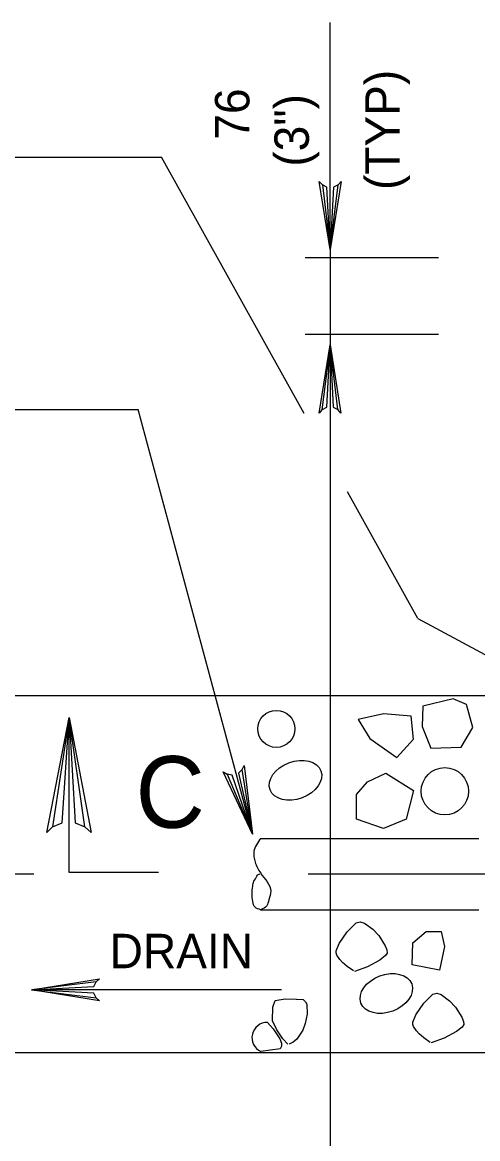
# Model space of a CAD drawing. Extents: x 638455 to 640199, y 298558 to 299152.
# Drawn here: x 639410.6 to 639455, y 298979.8 to 299088.8 of the extents above; entities that cross this region are included whole.
import ezdxf

# ---------------------------------------------------------------- set-up
doc = ezdxf.new("R2010")
doc.units = 0
for name, color, linetype in [('1', 7, 'Continuous'), ('2', 7, 'Continuous'), ('3', 7, 'Continuous')]:
    doc.layers.add(name, color=color, linetype=linetype)

msp = doc.modelspace()

# ---------------------------------------------------------------- linework, layer by layer
at = {"layer": '1'}
for p, q in [((639438.04, 299050.57), (639424.14, 299075.6)), ((639433.02, 299009.51), (639421.85, 299050.97)), ((639449.14, 299030.57), (639442.29, 299042.92))]:
    msp.add_line(p, q, dxfattribs=at)
for points in [[(639452.58, 299022.71), (639449.64, 299022.01), (639449.56, 299020), (639450.41, 299017.91), (639453.36, 299017.98), (639454.52, 299019.92), (639453.9, 299022.17)], [(639447.1, 299016.99), (639448.73, 299018.77), (639448.5, 299021.01), (639445.79, 299021.25), (639443.31, 299020.7), (639444.47, 299018.85)], [(639443.15, 299010.96), (639443.15, 299013.36), (639444.23, 299014.6), (639446.01, 299015.46), (639448.72, 299013.75), (639448.02, 299010.96), (639445.78, 299010.04)], [(639448.58, 298996.73), (639448.67, 298998.88), (639449.96, 298999.99), (639451.42, 298999.99), (639451.76, 298998.53), (639451.25, 298996.21)]]:
    msp.add_lwpolyline(points, close=True, dxfattribs=at)
for centre, radius in [((639435.34, 299019.78), 1.81), ((639451.78, 299013.69), 2.31)]:
    msp.add_circle(centre, radius, dxfattribs=at)
msp.add_arc((639434.45, 298989.63), 1.49, 89.5919, 244.8137, dxfattribs=at)
for centre in [(639437.21, 299014.76), (639446.07, 298993.94)]:
    msp.add_ellipse(centre, major_axis=(-2.48, -0.93), ratio=0.690668, dxfattribs=at)
at = {"layer": '2'}
for p, q in [((639440.59, 299066.59), (639440.59, 299088.77)), ((639395.61, 299075.6), (639424.14, 299075.6)), ((639451.15, 299065.79), (639438.15, 299065.79)), ((639440.59, 299066.59), (639440.59, 298952.92)), ((639451.15, 299058.29), (639438.15, 299058.29)), ((639391.01, 299050.97), (639421.85, 299050.97)), ((639449.14, 299030.57), (639476.21, 299015.92)), ((639373.94, 299023.03), (639513.29, 299023.03)), ((639415.11, 299005.77), (639415.11, 299020.89)), ((639433.8, 299009.09), (639455.11, 299009.09)), ((639367.29, 299005.61), (639411.68, 299005.61)), ((639423.83, 299005.77), (639415.11, 299005.77)), ((639438.43, 299005.61), (639589.81, 299005.61)), ((639433.8, 299002.12), (639455.11, 299002.12)), ((639373.95, 298988.18), (639513.29, 298988.18))]:
    msp.add_line(p, q, dxfattribs=at)
for points in [[(639441.38, 299072.92), (639440.92, 299072.68), (639440.59, 299066.59), (639441.38, 299072.92), (639441.66, 299073.24), (639440.59, 299066.59), (639440.28, 299072.68), (639439.83, 299072.9), (639440.59, 299066.59), (639439.53, 299073.24), (639439.83, 299072.9)], [(639439.79, 299050.94), (639440.25, 299051.18), (639440.59, 299057.28), (639439.79, 299050.94), (639439.51, 299050.62), (639440.59, 299057.28), (639440.89, 299051.19), (639441.34, 299050.96), (639440.59, 299057.28), (639441.64, 299050.62), (639441.34, 299050.96)], [(639413.5, 299010.2), (639414.43, 299010.59), (639415.11, 299020.89), (639413.5, 299010.2), (639412.94, 299009.65), (639415.11, 299020.89), (639415.72, 299010.6), (639416.65, 299010.23), (639415.11, 299020.89), (639417.26, 299009.65), (639416.65, 299010.23)], [(639432.01, 299015.8), (639431.64, 299015.45), (639433.02, 299009.51), (639432.01, 299015.8), (639432.19, 299016.19), (639433.02, 299009.51), (639431.03, 299015.27), (639430.53, 299015.35), (639433.02, 299009.51), (639430.14, 299015.6), (639430.53, 299015.35)], [(639442.25, 298999.96), (639443.13, 299000.84)], [(639443.13, 299000.84), (639443.52, 299000.94)], [(639443.52, 299000.94), (639443.95, 299000.81)], [(639443.95, 299000.81), (639444.75, 299000.21)], [(639444.75, 299000.21), (639445.33, 298999.59)], [(639441.47, 298998.82), (639442.25, 298999.96)], [(639445.33, 298999.59), (639445.97, 298998.61)], [(639441.17, 298997.9), (639441.18, 298998.11)], [(639441.18, 298998.11), (639441.47, 298998.82)], [(639445.97, 298998.61), (639446.13, 298998.19)], [(639446.13, 298998.19), (639446.14, 298997.88)], [(639441.23, 298997.68), (639441.17, 298997.9)], [(639441.52, 298997.25), (639441.23, 298997.68)], [(639441.81, 298996.96), (639441.52, 298997.25)], [(639442.25, 298996.59), (639441.81, 298996.96)], [(639445.45, 298997.19), (639444.24, 298996.56)], [(639445.99, 298997.64), (639445.45, 298997.19)], [(639446.14, 298997.88), (639445.99, 298997.64)], [(639442.87, 298996.14), (639442.25, 298996.59)], [(639444.24, 298996.56), (639442.96, 298996.08)], [(639417.77, 298993.52), (639417.53, 298993.98), (639411.44, 298994.31), (639417.77, 298993.52), (639418.09, 298993.24), (639411.44, 298994.31), (639417.53, 298994.62), (639417.75, 298995.07), (639411.44, 298994.31), (639418.09, 298995.37), (639417.75, 298995.07)], [(639435.83, 298994.31), (639418.41, 298994.31), (639411.44, 298994.31)], [(639449.73, 298992.99), (639450.61, 298993.87)], [(639450.61, 298993.87), (639451, 298993.97)], [(639451, 298993.97), (639451.43, 298993.84)], [(639451.43, 298993.84), (639452.23, 298993.24)], [(639434.98, 298991.29), (639435, 298992.62)], [(639435, 298992.62), (639435.24, 298993.27)], [(639435.24, 298993.27), (639436.2, 298993.42)], [(639436.2, 298993.42), (639437.28, 298993.4)], [(639437.32, 298993.4), (639437.97, 298993.36)], [(639437.97, 298993.36), (639438.2, 298993.12)], [(639438.2, 298993.12), (639438.32, 298992.89)], [(639438.32, 298992.89), (639438.35, 298991.91)], [(639448.95, 298991.85), (639449.73, 298992.99)], [(639452.23, 298993.24), (639452.81, 298992.62)], [(639452.81, 298992.62), (639453.45, 298991.64)], [(639438.35, 298991.91), (639438.16, 298991.02)], [(639448.67, 298991.14), (639448.95, 298991.85)], [(639453.45, 298991.64), (639453.61, 298991.22)], [(639434.46, 298991.12), (639435.04, 298990.49)], [(639435.38, 298990.38), (639434.97, 298991.28)], [(639435.04, 298990.49), (639435.68, 298989.51)], [(639435.96, 298989.5), (639435.38, 298990.38)], [(639437.91, 298990.35), (639437.35, 298989.49)], [(639438.16, 298991.02), (639437.91, 298990.35)], [(639448.65, 298990.93), (639448.67, 298991.14)], [(639448.72, 298990.71), (639448.65, 298990.93)], [(639449.01, 298990.28), (639448.72, 298990.71)], [(639453.47, 298990.67), (639452.93, 298990.22)], [(639453.62, 298990.91), (639453.47, 298990.67)], [(639453.61, 298991.22), (639453.62, 298990.91)], [(639435.68, 298989.51), (639435.84, 298989.1)], [(639436.47, 298988.98), (639435.96, 298989.5)], [(639437.35, 298989.49), (639436.99, 298989.18)], [(639449.29, 298989.99), (639449.01, 298990.28)], [(639449.73, 298989.62), (639449.29, 298989.99)], [(639450.35, 298989.17), (639449.73, 298989.62)], [(639451.72, 298989.59), (639450.44, 298989.11)], [(639452.93, 298990.22), (639451.72, 298989.59)], [(639435.7, 298988.54), (639433.81, 298988.28)], [(639435.85, 298988.79), (639435.7, 298988.54)], [(639435.84, 298989.1), (639435.85, 298988.79)], [(639436.99, 298989.18), (639436.58, 298988.98)]]:
    msp.add_lwpolyline(points, dxfattribs=at)
for points in [[(639433.8, 299009.09), (639433.15, 299007.81), (639433.27, 299006.78), (639433.81, 299005.69), (639434.79, 299003.93), (639434.6, 299003.08), (639434.4, 299002.5), (639433.8, 299002.12)], [(639433.8, 299002.12), (639433.27, 299002.37), (639433.03, 299002.91), (639432.97, 299003.7), (639433.03, 299004.42), (639433.15, 299004.9), (639433.45, 299005.39), (639433.57, 299005.57), (639433.76, 299005.63)]]:
    msp.add_spline(points, degree=3, dxfattribs=at)

# ---------------------------------------------------------------- texts
at = {"layer": '1'}
msp.add_text('(3")', height=3.36, rotation=90, dxfattribs=at).set_placement((639438.51, 299074.68))
at = {"layer": '3'}
for s, p in [('(TYP)', (639447.38, 299072.4)), ('76', (639432.71, 299077.32))]:
    msp.add_text(s, height=3.36, rotation=90, dxfattribs=at).set_placement(p)
for s, height, p in [('C', 7, (639421.6, 299010.12)), ('DRAIN', 3.36, (639419.08, 298996.41))]:
    msp.add_text(s, height=height, dxfattribs=at).set_placement(p)

doc.saveas('drawing.dxf')
